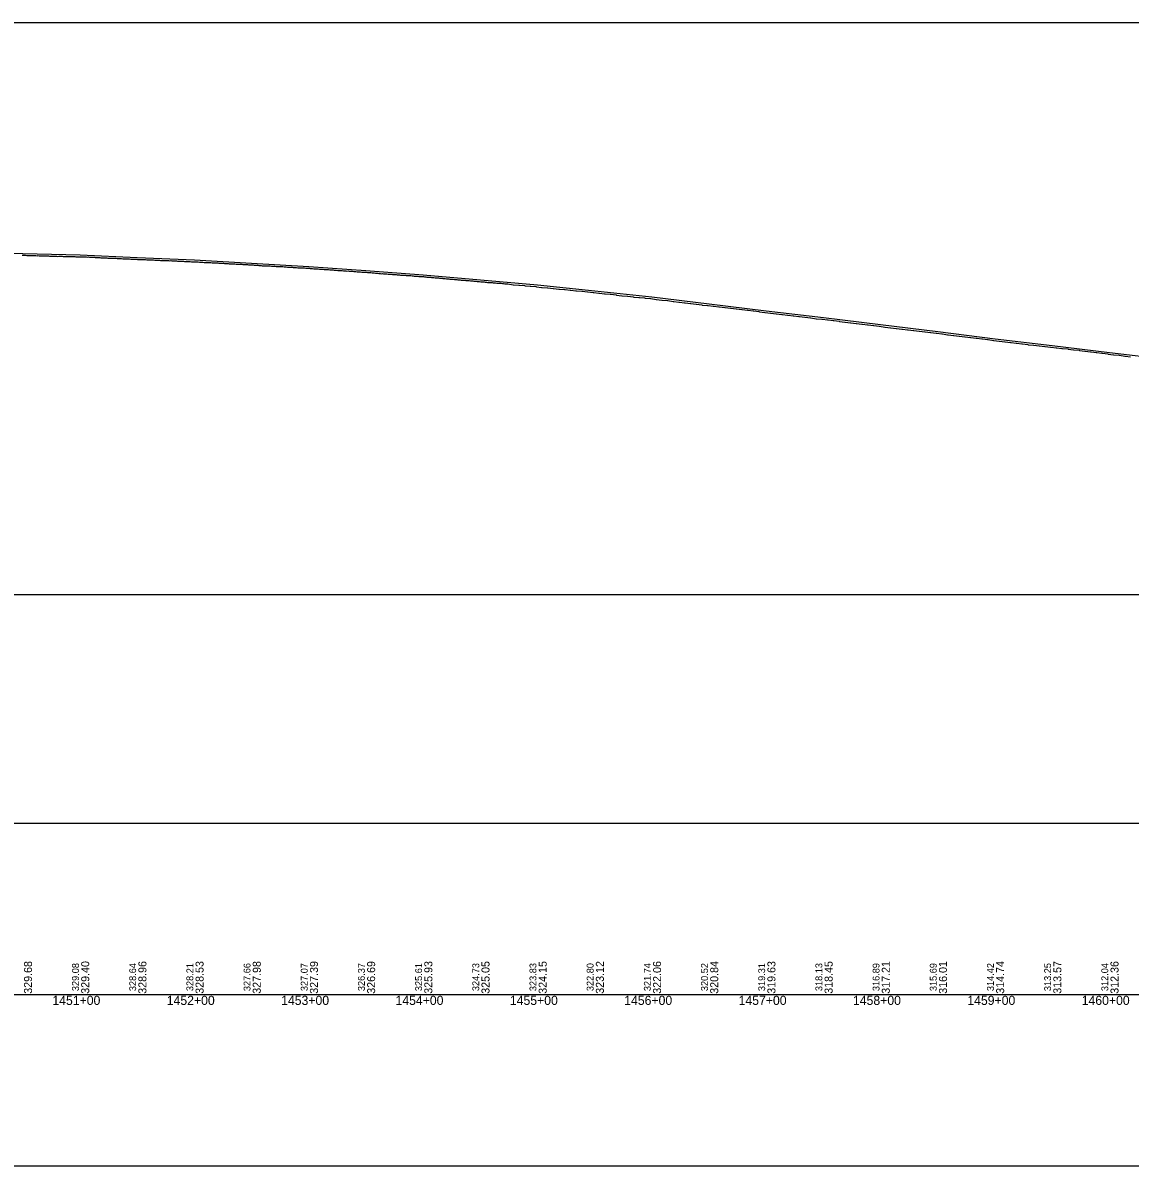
# Model space of a CAD drawing. Extents: x -3627 to 47473, y 2850 to 4350.
# Drawn here: x 32527 to 33495, y 2850 to 3850 of the extents above; entities that cross this region are included whole.
import ezdxf

# ---------------------------------------------------------------- set-up
doc = ezdxf.new("R2010")
doc.units = 0
for name, color, linetype in [('RD_DDB_Profile_EX', 7, 'Continuous'), ('RD_DDB_Profile_PR', 7, 'Continuous'), ('RD_DDB_StaTX', 7, 'Continuous'), ('RD_DDB_StripGrade', 7, 'Continuous'), ('RD_GPK_Profile_Cell', 7, 'Continuous'), ('RD_SHT_ShtClip', 7, 'Continuous')]:
    doc.layers.add(name, color=color, linetype=linetype)

msp = doc.modelspace()

# ---------------------------------------------------------------- linework, layer by layer
at = {"layer": 'RD_DDB_Profile_EX'}
for points in [[(32526.677699, 3646.810085), (32527.677715, 3646.80448), (32528.677731, 3646.7603), (32529.677747, 3646.71611), (32530.677764, 3646.58332), (32531.67778, 3646.57772), (32532.677796, 3646.539215), (32533.677813, 3646.52792), (32534.677829, 3646.516635), (32535.677845, 3646.47812), (32536.677862, 3646.52822), (32537.677878, 3646.484005), (32538.677894, 3646.38978), (32539.67791, 3646.334195), (32540.677927, 3646.37294), (32541.677943, 3646.36737), (32542.677959, 3646.328815), (32543.677976, 3646.284585), (32544.677992, 3646.24035), (32545.677327, 3646.186485), (32546.677343, 3646.22535), (32547.677359, 3646.181065), (32548.677375, 3646.125555), (32549.677392, 3646.12005), (32550.677408, 3646.07576), (32551.67751, 3646.075635), (32552.677527, 3646.02013), (32553.677543, 3645.98705), (32554.677559, 3645.89835), (32555.621569, 3645.898535), (32556.621641, 3645.931625), (32557.621712, 3645.748315), (32558.621783, 3645.792595), (32559.621825, 3645.909075), (32560.621897, 3645.864545), (32561.621968, 3645.83124), (32562.62204, 3645.775505), (32563.622081, 3645.72561), (32564.622388, 3645.773675), (32565.62246, 3645.77921), (32566.622531, 3645.767755), (32567.622573, 3645.717865), (32568.622645, 3645.66773), (32569.622717, 3645.6676)], [(32569.622717, 3645.6676), (32570.622789, 3645.62314), (32571.62283, 3645.578915), (32572.622902, 3645.52879), (32573.62321, 3645.47689), (32574.623283, 3645.426765), (32575.623324, 3645.465425), (32576.623397, 3645.42674), (32577.623469, 3645.37661), (32578.623541, 3645.37648), (32579.623583, 3645.365125), (32580.623655, 3645.36499), (32581.623964, 3645.31877), (32582.624037, 3645.230205), (32583.624079, 3645.1803), (32584.622994, 3645.212815), (32585.623066, 3645.11268), (32586.623138, 3644.974125), (32587.623181, 3644.935805), (32588.623253, 3644.97989), (32589.623325, 3644.92976), (32590.623596, 3644.87228), (32591.623668, 3644.80462), (32592.62374, 3644.74863), (32593.623813, 3644.72773), (32594.623855, 3644.721985), (32595.623927, 3644.62185), (32596.624, 3644.571715), (32597.624072, 3644.483295), (32598.624114, 3644.47168), (32599.624416, 3644.469755), (32600.624489, 3644.38143), (32601.624562, 3644.3313), (32602.624604, 3644.2814), (32603.624677, 3644.28127), (32604.62475, 3644.187055), (32605.624822, 3644.17509), (32606.624864, 3644.131105), (32607.624937, 3644.092815), (32608.625241, 3644.0851), (32609.625314, 3643.984975), (32610.625356, 3643.94104), (32611.655285, 3643.89694), (32612.655376, 3643.852795), (32613.655404, 3643.852885), (32614.655433, 3643.526855), (32615.655462, 3643.564995), (32616.65549, 3643.60911), (32617.655519, 3643.64131), (32618.65601, 3643.63378), (32619.656101, 3643.527635), (32620.65613, 3643.48374), (32621.656159, 3643.445845), (32622.656187, 3643.439935), (32623.656216, 3643.39003), (32624.656244, 3643.34012), (32625.656273, 3643.29621), (32626.656364, 3643.21408), (32627.656393, 3643.158165), (32628.656422, 3643.15825), (32629.656913, 3643.068925), (32630.656941, 3643.019005), (32631.65697, 3643.050995), (32632.656998, 3642.951085), (32633.657027, 3642.95117), (32634.657119, 3642.938995), (32635.657147, 3642.85114), (32636.657176, 3642.763275), (32637.657205, 3642.763355), (32638.657233, 3642.7514), (32639.648469, 3642.69546), (32640.648497, 3642.607575), (32641.649062, 3642.59385), (32642.64909, 3642.418185), (32643.649118, 3642.412205), (32644.649146, 3642.418345), (32645.649174, 3642.418425), (32646.649202, 3642.362455), (32647.64923, 3642.262535), (32648.649323, 3642.20637), (32649.649351, 3642.11855), (32650.649379, 3642.10654), (32651.649407, 3642.056625), (32652.649907, 3642.049145), (32653.649935, 3642.049235), (32654.649963, 3642.0054), (32655.650056, 3641.95528), (32656.650084, 3641.999285), (32657.650112, 3641.899375), (32658.65014, 3641.84946), (32659.650168, 3641.7617), (32660.650196, 3641.75571), (32661.650224, 3641.743655), (32662.650317, 3641.61175), (32663.650345, 3641.64969), (32664.650845, 3641.604365), (32665.650873, 3641.55445), (32666.650901, 3641.504535), (32667.650929, 3641.45462), (32668.650957, 3641.404705), (32669.65105, 3641.354585)], [(32669.65105, 3641.354585), (32670.651078, 3641.342465), (32671.651106, 3641.298655), (32672.710838, 3641.173235), (32673.709914, 3641.194425), (32674.709916, 3641.10056), (32675.709917, 3641.094605), (32676.709919, 3641.03262), (32677.709921, 3641.03875), (32678.709796, 3640.939065), (32679.709797, 3640.88916), (32680.709799, 3640.839255), (32681.709801, 3640.78333), (32682.709803, 3640.77741), (32683.709805, 3640.689535), (32684.708879, 3640.635285), (32685.70888, 3640.491345), (32686.708882, 3640.403355), (32687.708758, 3640.40365), (32688.70876, 3640.39779), (32689.708762, 3640.34788), (32690.708764, 3640.29203), (32691.708766, 3640.280245), (32692.708767, 3640.230345), (32693.708769, 3640.030445), (32694.707841, 3640.03226), (32695.707843, 3640.07648), (32696.707721, 3639.976815), (32697.707723, 3639.98866), (32698.707725, 3639.90049), (32699.707726, 3639.78885), (32700.707728, 3639.783085), (32701.70773, 3639.771465), (32702.707732, 3639.677425), (32703.707734, 3639.627525), (32704.706682, 3639.57383), (32705.706684, 3639.56234), (32706.706685, 3639.456655), (32707.706687, 3639.36835), (32708.706689, 3639.235825), (32709.706691, 3639.18592), (32710.706693, 3639.180235), (32711.706695, 3639.12456), (32712.706696, 3639.168885), (32713.706577, 3639.019235), (32714.706578, 3638.96934), (32715.705648, 3638.92131), (32716.70565, 3638.87142), (32717.705652, 3638.871525), (32718.705654, 3638.82163), (32719.705655, 3638.72174), (32720.705657, 3638.71614), (32721.705659, 3638.627655), (32722.705541, 3638.5723), (32723.69669, 3638.522385), (32724.696691, 3638.47249), (32725.69575, 3638.424465), (32726.695751, 3638.33021), (32727.695752, 3638.280315), (32728.695753, 3638.269155), (32729.695755, 3638.041775), (32730.695636, 3638.036475), (32731.695638, 3637.986575), (32732.695639, 3637.93668), (32733.69564, 3637.88117), (32734.695642, 3637.814445), (32735.695643, 3637.77577), (32736.695644, 3637.592685), (32737.694701, 3637.544515), (32738.694702, 3637.594615), (32739.694585, 3637.583845), (32740.694587, 3637.45057), (32741.694588, 3637.3562), (32742.651448, 3637.345135), (32743.65147, 3637.3397), (32744.65142, 3637.2845), (32745.651442, 3637.22908), (32746.651464, 3637.095745), (32747.651486, 3637.13481), (32748.651509, 3637.04043), (32749.65095, 3636.95324), (32750.650972, 3636.89241), (32751.650994, 3636.88159), (32752.650945, 3636.83193), (32753.650967, 3636.876585), (32754.650989, 3636.78214), (32755.651012, 3636.62136), (32756.651034, 3636.626915), (32757.651056, 3636.58246), (32758.651078, 3636.44344), (32759.6511, 3636.39354), (32760.65047, 3636.340265), (32761.650492, 3636.251115), (32762.650514, 3636.24047), (32763.650537, 3636.151315), (32764.650559, 3635.97288), (32765.650581, 3635.94078), (32766.650603, 3635.935525), (32767.650625, 3635.84635), (32768.650578, 3635.752015), (32769.6506, 3635.83072)], [(32769.6506, 3635.83072), (32770.650622, 3635.74152), (32771.650644, 3635.691625), (32772.650084, 3635.638265), (32773.650106, 3635.633085), (32774.650128, 3635.527905), (32775.65015, 3635.4833), (32776.650172, 3635.438695), (32777.650126, 3635.29957), (32778.650148, 3635.183855), (32779.65017, 3635.049775), (32780.650192, 3635.04461), (32781.650215, 3634.984185), (32782.650237, 3634.789555), (32783.650259, 3634.83966), (32784.650281, 3634.839765), (32785.650235, 3634.74534), (32786.650257, 3634.684955), (32787.650279, 3634.67458), (32788.650302, 3634.585175), (32789.650324, 3634.530045), (32790.650346, 3634.390625), (32791.650368, 3634.295965), (32792.650391, 3634.28561), (32793.650345, 3634.185945), (32794.650367, 3634.13605), (32795.650389, 3634.0153), (32796.64937, 3634.02063), (32797.649392, 3633.931165), (32798.649415, 3633.87607), (32799.649438, 3633.55221), (32800.640507, 3633.54709), (32801.640462, 3633.547405), (32802.640484, 3633.47674), (32803.640506, 3633.482045), (32804.640529, 3633.476965), (32805.640551, 3633.38745), (32806.640573, 3633.28756), (32807.640595, 3633.192845), (32808.640618, 3633.04295), (32809.640573, 3633.048445), (32810.640595, 3632.938215), (32811.640618, 3632.98316), (32812.64064, 3632.87811), (32813.640662, 3632.78854), (32814.590157, 3632.74391), (32815.590205, 3632.694015), (32816.590254, 3632.59927), (32817.590288, 3632.54444), (32818.590336, 3632.399685), (32819.590385, 3632.294655), (32820.590433, 3632.20502), (32821.590467, 3632.205325), (32822.590516, 3632.155425), (32823.590564, 3632.06576), (32824.590598, 3632.06605), (32825.590647, 3632.00593), (32826.590695, 3631.900925), (32827.590743, 3631.80613), (32828.590778, 3631.66662), (32829.590826, 3631.661625), (32830.590875, 3631.61172), (32831.590909, 3631.506935), (32832.590958, 3631.44688), (32833.591006, 3631.307135), (32834.591041, 3631.257435), (32835.591089, 3631.15247), (32836.591137, 3631.1127), (32837.591186, 3630.927975), (32838.59122, 3630.863085), (32839.591269, 3630.803085), (32840.591317, 3630.61328), (32841.692123, 3630.698465), (32842.591521, 3630.606865), (32843.59157, 3630.601885), (32844.591618, 3630.54183), (32845.591653, 3630.397225), (32846.591701, 3630.30746), (32847.591749, 3630.24743), (32848.582796, 3630.147725), (32849.683928, 3630.137735), (32850.583022, 3629.82157), (32851.58307, 3629.835995), (32852.583103, 3629.881235), (32853.583151, 3629.84152), (32854.583199, 3629.741625), (32855.583232, 3629.686875), (32856.684716, 3629.61671), (32857.583457, 3629.390265), (32858.583505, 3629.38526), (32859.583538, 3629.3458), (32860.583586, 3629.301005), (32861.583634, 3629.27561), (32862.583667, 3629.131045), (32863.583715, 3628.991335), (32864.685498, 3628.926195), (32865.58394, 3628.8794), (32866.582949, 3628.879735), (32867.582998, 3628.729845), (32868.583046, 3628.629955), (32869.583081, 3628.580295)], [(32869.583081, 3628.580295), (32870.583129, 3628.5253), (32871.583178, 3628.475415), (32872.583332, 3628.423735), (32873.58338, 3628.27385), (32874.583429, 3628.1791), (32875.583477, 3628.129215), (32876.583512, 3628.02955), (32877.583561, 3628.024535), (32878.583609, 3627.834895), (32879.685919, 3627.735235), (32880.583811, 3627.643725), (32881.58386, 3627.53867), (32882.676543, 3627.483835), (32883.676437, 3627.429025), (32884.67644, 3627.329135), (32885.676334, 3627.239725), (32886.676336, 3627.13983), (32887.677169, 3627.08312), (32888.677171, 3627.022905), (32889.677066, 3626.8784), (32890.667999, 3626.868425), (32891.666974, 3626.63911), (32892.666869, 3626.644565), (32893.666871, 3626.62927), (32894.666767, 3626.484725), (32895.667702, 3626.422595), (32896.667598, 3626.367775), (32897.6676, 3626.22305), (32898.667496, 3626.16824), (32899.668428, 3626.116325), (32900.668323, 3625.937415), (32901.668326, 3625.83752), (32902.668222, 3625.698185), (32903.668118, 3625.688155), (32904.669046, 3625.670785), (32905.668942, 3625.57113), (32906.668945, 3625.47124), (32907.668841, 3625.37677), (32908.669766, 3625.274955), (32909.669661, 3625.22529), (32910.669664, 3624.98062), (32911.66956, 3625.0153), (32912.669563, 3624.970625), (32913.670378, 3624.969005), (32914.669333, 3624.729605), (32915.66923, 3624.66945), (32916.669128, 3624.56979), (32917.670038, 3624.5574), (32918.669935, 3624.46829), (32919.661001, 3624.32364), (32920.660897, 3624.26872), (32921.660901, 3624.13459), (32922.661708, 3624.083095), (32923.661712, 3623.962045), (32924.661608, 3623.82823), (32925.661612, 3623.69417), (32926.662416, 3623.671495), (32927.662312, 3623.621825), (32928.662316, 3623.56663), (32929.662213, 3623.422265), (32930.662216, 3623.411785), (32931.663017, 3623.186805), (32932.663021, 3623.13158), (32933.662918, 3623.031895), (32934.662922, 3622.92668), (32935.663719, 3622.8984), (32936.663723, 3622.859215), (32937.66362, 3622.764905), (32938.662557, 3622.665015), (32939.663344, 3622.61881), (32940.663242, 3622.563775), (32941.663247, 3622.41388), (32942.663145, 3622.40886), (32943.66315, 3622.303615), (32944.663934, 3622.19658), (32945.663939, 3622.19131), (32946.654923, 3621.92395), (32947.654927, 3621.91329), (32948.655715, 3621.861725), (32949.547457, 3621.77265), (32950.697083, 3621.6899), (32951.437236, 3621.60048), (32955.899847, 3620.97816), (32956.437049, 3620.934625), (32960.903673, 3620.668785), (32961.436858, 3620.614855), (32965.907528, 3620.17016), (32966.435604, 3620.12194), (32970.910356, 3619.766295), (32971.435414, 3619.707905), (32975.914275, 3619.30732), (32976.435221, 3619.24936), (32980.909215, 3618.66917), (32981.425886, 3618.627895), (32985.914531, 3618.271165), (32986.425383, 3618.215485), (32990.920743, 3617.768475), (32991.424825, 3617.70874), (32995.927378, 3617.126035), (32996.424326, 3617.086745)], [(32996.424326, 3617.086745), (33000.93356, 3616.77347), (33001.423773, 3616.73004), (33005.940152, 3616.28087), (33006.423278, 3616.218565), (33010.946304, 3615.723665), (33011.421781, 3615.681475), (33015.95191, 3615.230985), (33016.421303, 3615.1892), (33020.954103, 3614.781765), (33021.421281, 3614.72174), (33025.960626, 3614.1343), (33026.420858, 3614.09773), (33030.966338, 3613.645595), (33031.420588, 3613.567995), (33035.957791, 3613.11393), (33036.411738, 3613.09997), (33040.962333, 3612.60183), (33041.411454, 3612.561095), (33045.9669, 3611.971195), (33046.410276, 3611.92648), (33050.966615, 3611.38018), (33051.41051, 3611.32218), (33055.971227, 3610.913945), (33056.410277, 3610.869565), (33060.971459, 3610.231485), (33061.410509, 3610.178515), (33065.97611, 3609.81546), (33066.410221, 3609.77175), (33070.971602, 3609.408405), (33071.399936, 3609.33508), (33075.971378, 3608.832815), (33076.400067, 3608.807145), (33080.976846, 3608.168925), (33081.399675, 3608.12246), (33085.982323, 3607.574915), (33086.39933, 3607.512235), (33090.983356, 3607.100205), (33091.399461, 3607.066965), (33095.980678, 3606.42417), (33096.400116, 3606.3655), (33100.972875, 3605.816175), (33101.391137, 3605.77841), (33105.969834, 3605.04451), (33106.390956, 3604.993915), (33110.966317, 3604.58092), (33111.391611, 3604.50442), (33115.967719, 3604.001595), (33116.391742, 3603.9762), (33120.965055, 3603.243165), (33121.392445, 3603.20032), (33125.962013, 3602.74223), (33126.393099, 3602.673305), (33130.963414, 3602.26246), (33131.393181, 3602.20683), (33135.951964, 3601.6572), (33136.384704, 3601.613975), (33140.95336, 3600.974875), (33141.383922, 3600.92763), (33145.950229, 3600.515355), (33146.384574, 3600.45894), (33150.947588, 3599.81871), (33151.385175, 3599.766425), (33155.949369, 3599.310505), (33156.385308, 3599.249525), (33160.946735, 3598.65506), (33161.385908, 3598.58944), (33165.948514, 3598.133745), (33166.385166, 3598.08567), (33170.935841, 3597.400115), (33171.376645, 3597.347465), (33175.933611, 3596.708025), (33176.377293, 3596.645965), (33180.934999, 3596.145155), (33181.377376, 3596.10558), (33185.932777, 3595.46643), (33186.377974, 3595.413235), (33190.934552, 3595.049195), (33191.378057, 3594.987365), (33195.92319, 3594.348225), (33196.368658, 3594.299365), (33200.920089, 3593.751765), (33201.369253, 3593.69362), (33205.921861, 3593.19337), (33206.369337, 3593.144395), (33210.919667, 3592.5514), (33211.36993, 3592.497615), (33215.921435, 3591.99747), (33216.370014, 3591.930445), (33220.9232, 3591.24804), (33221.369207, 3591.20805), (33225.918871, 3590.80011), (33226.359681, 3590.76067), (33230.920628, 3590.168245), (33231.359816, 3590.10681), (33235.925964, 3589.606955), (33236.359538, 3589.54592), (33240.930565, 3588.95428), (33241.359257, 3588.9111), (33245.931198, 3588.317265), (33246.359487, 3588.265565)], [(33246.359487, 3588.265565), (33250.935834, 3587.764555), (33251.358306, 3587.71786), (33255.930816, 3587.124615), (33256.34887, 3587.065785), (33260.93147, 3586.516395), (33261.349097, 3586.46597), (33265.936165, 3585.872115), (33266.348804, 3585.8223), (33270.940886, 3585.27367), (33271.348507, 3585.216295), (33275.941561, 3584.66567), (33276.348685, 3584.61261), (33280.946676, 3583.9255), (33281.34758, 3583.864935), (33285.937316, 3583.35958), (33286.338613, 3583.33522), (33290.938006, 3582.737795), (33291.338882, 3582.68123), (33295.934232, 3582.12841), (33296.339634, 3582.087595), (33300.934916, 3581.582595), (33301.339904, 3581.517315), (33305.931118, 3580.91898), (33306.340706, 3580.87756), (33310.931428, 3580.4649), (33311.34011, 3580.415445), (33315.917927, 3579.81763), (33316.331741, 3579.76748), (33320.914089, 3579.307775), (33321.332548, 3579.23607), (33325.914375, 3578.64105), (33326.332774, 3578.607245), (33330.910891, 3577.919015), (33331.333584, 3577.876275), (33335.911165, 3577.235915), (33336.333811, 3577.184915), (33340.907662, 3576.680495), (33341.33367, 3576.629145), (33345.903677, 3576.07942), (33346.334228, 3576.02814), (33350.896701, 3575.434305), (33351.325071, 3575.374895), (33355.895151, 3574.825135), (33356.325631, 3574.769575), (33360.897346, 3574.175765), (33361.325661, 3574.124755), (33365.89542, 3573.57504), (33366.32617, 3573.523915), (33370.89799, 3573.067225), (33371.326202, 3573.01625), (33375.900165, 3572.28494), (33376.325336, 3572.2216), (33380.90186, 3571.718685), (33381.325374, 3571.65981), (33385.894821, 3571.01933), (33386.316259, 3570.96495), (33390.896971, 3570.369985), (33391.316342, 3570.31988), (33395.902813, 3569.86367), (33396.316045, 3569.822045), (33400.903481, 3569.226195), (33401.31627, 3569.1681), (33405.90415, 3568.52633), (33406.315717, 3568.476375), (33410.903624, 3568.109845), (33411.315943, 3568.068305), (33415.904297, 3567.47235), (33416.316169, 3567.435), (33420.89575, 3566.97659), (33421.307224, 3566.93516), (33425.896425, 3566.430835), (33426.307497, 3566.38105), (33430.896732, 3565.876735), (33431.306898, 3565.82712), (33435.896585, 3565.27687), (33436.307124, 3565.235535), (33440.897265, 3564.777005), (33441.307349, 3564.73161), (33445.893772, 3564.08816), (33446.308149, 3564.033845), (33450.88989, 3563.57433), (33451.308902, 3563.51535), (33455.877179, 3562.9188), (33456.299663, 3562.863445), (33460.876988, 3562.36048), (33461.29989, 3562.31787), (33465.87346, 3561.767605), (33466.300697, 3561.70727), (33470.869528, 3561.066135), (33471.301455, 3561.013985), (33475.86598, 3560.419165), (33476.301341, 3560.357755), (33480.852375, 3559.717855), (33481.29298, 3559.66907), (33485.848811, 3559.25766), (33486.293793, 3559.19926), (33490.849024, 3558.562085), (33491.294025, 3558.50835), (33495.84544, 3557.86972)]]:
    msp.add_lwpolyline(points, dxfattribs=at)
at = {"layer": 'RD_DDB_Profile_PR'}
for points in [[(32477.33, 3649.5715), (32527.33, 3648.4065), (32577.33, 3646.9915), (32627.33, 3644.7765), (32677.33, 3642.6365), (32727.33, 3639.8985), (32777.33, 3636.944), (32827.33, 3633.431), (32877.33, 3629.626), (32927.33, 3625.2385), (32977.33, 3620.7335), (33027.33, 3615.6075), (33077.33, 3610.2775), (33127.33, 3604.189), (33177.33, 3598.1415)], [(33177.33, 3598.1415), (33227.33, 3592.2345), (33277.33, 3586.066), (33327.33, 3580.0575), (33377.33, 3573.711), (33427.33, 3567.8685), (33477.33, 3561.813), (33527.33, 3555.7105)]]:
    msp.add_lwpolyline(points, dxfattribs=at)
at = {"layer": 'RD_GPK_Profile_Cell'}
msp.add_line((1000, 3000), (46705.077602, 3000), dxfattribs=at)
at = {"layer": 'RD_SHT_ShtClip'}
for points in [[(32453.33, 3850), (32453.33, 3350), (33953.33, 3350), (33953.33, 3350), (33953.33, 3850), (33953.33, 3850)], [(32433.33, 3150), (33973.33, 3150), (33973.33, 2850), (32433.33, 2850)]]:
    msp.add_lwpolyline(points, close=True, dxfattribs=at)

# ---------------------------------------------------------------- texts
at = {"layer": 'RD_DDB_StaTX'}
for s, p in [('1451+00', (32553.125471, 2991)), ('1452+00', (32653.125471, 2991)), ('1453+00', (32753.125471, 2991)), ('1454+00', (32853.125471, 2991)), ('1455+00', (32953.125471, 2991)), ('1456+00', (33053.125471, 2991)), ('1457+00', (33153.125471, 2991)), ('1458+00', (33253.125471, 2991)), ('1459+00', (33353.125471, 2991)), ('1460+00', (33453.125471, 2991))]:
    msp.add_text(s, height=8, dxfattribs=at).set_placement(p)
at = {"layer": 'RD_DDB_StripGrade'}
for s, height, p in [('329.68', 7, (32535.33, 3000.75)), ('329.08', 6, (32576.33, 3003.073688)), ('329.40', 7, (32585.33, 3000.75)), ('328.64', 6, (32626.33, 3003.073688)), ('328.96', 7, (32635.33, 3000.75)), ('328.21', 6, (32676.33, 3003.073688)), ('328.53', 7, (32685.33, 3000.75)), ('327.66', 6, (32726.33, 3003.073688)), ('327.98', 7, (32735.33, 3000.75)), ('327.07', 6, (32776.33, 3003.073688)), ('327.39', 7, (32785.33, 3000.75)), ('326.37', 6, (32826.33, 3003.073688)), ('326.69', 7, (32835.33, 3000.75)), ('325.61', 6, (32876.33, 3003.073688)), ('325.93', 7, (32885.33, 3000.75)), ('324.73', 6, (32926.33, 3003.073688)), ('325.05', 7, (32935.33, 3000.75)), ('323.83', 6, (32976.33, 3003.073688)), ('324.15', 7, (32985.33, 3000.75)), ('322.80', 6, (33026.33, 3003.073688)), ('323.12', 7, (33035.33, 3000.75)), ('321.74', 6, (33076.33, 3003.073688)), ('322.06', 7, (33085.33, 3000.75)), ('320.52', 6, (33126.33, 3003.073688)), ('320.84', 7, (33135.33, 3000.75)), ('319.31', 6, (33176.33, 3003.073688)), ('319.63', 7, (33185.33, 3000.75)), ('318.13', 6, (33226.33, 3003.073688)), ('318.45', 7, (33235.33, 3000.75)), ('316.89', 6, (33276.33, 3003.073688)), ('317.21', 7, (33285.33, 3000.75)), ('315.69', 6, (33326.33, 3003.073688)), ('316.01', 7, (33335.33, 3000.75)), ('314.42', 6, (33376.33, 3003.073688)), ('314.74', 7, (33385.33, 3000.75)), ('313.25', 6, (33426.33, 3003.073688)), ('313.57', 7, (33435.33, 3000.75)), ('312.04', 6, (33476.33, 3003.073688)), ('312.36', 7, (33485.33, 3000.75))]:
    msp.add_text(s, height=height, rotation=90, dxfattribs=at).set_placement(p)

doc.saveas('drawing.dxf')
